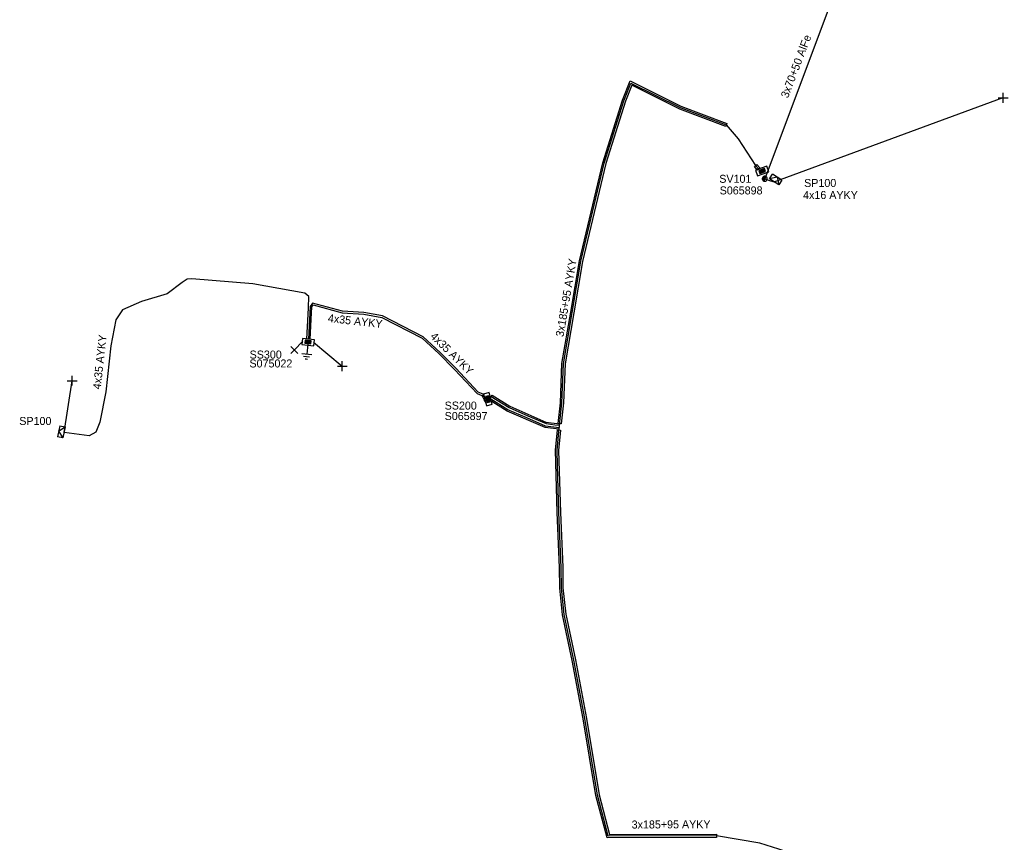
# Model space of a CAD drawing. Extents: x -788458 to -786145, y -1154772 to -1152372.
# Drawn here: x -787489.7 to -787366.2, y -1153095.6 to -1152992.9 of the extents above; entities that cross this region are included whole.
import ezdxf

# ---------------------------------------------------------------- set-up
doc = ezdxf.new("R2010")
doc.units = 0
for name, color, linetype in [('Vrstva 1', 7, 'Continuous'), ('Vrstva 13', 7, 'Continuous'), ('Vrstva 14', 7, 'Continuous'), ('Vrstva 15', 7, 'Continuous'), ('Vrstva 2', 7, 'Continuous'), ('Vrstva 20', 7, 'Continuous'), ('Vrstva 28', 7, 'Continuous'), ('Vrstva 29', 7, 'Continuous'), ('Vrstva 30', 7, 'Continuous'), ('Vrstva 31', 7, 'Continuous'), ('Vrstva 33', 7, 'Continuous'), ('Vrstva 34', 7, 'Continuous'), ('Vrstva 5', 7, 'Continuous'), ('Vrstva 52', 7, 'Continuous'), ('Vrstva 54', 7, 'Continuous'), ('Vrstva 59', 7, 'Continuous'), ('Vrstva 6', 7, 'Continuous'), ('Vrstva 8', 7, 'Continuous'), ('Vrstva 9', 7, 'Continuous')]:
    doc.layers.add(name, color=color, linetype=linetype)

# ---------------------------------------------------------------- blocks, each defined once
blk = doc.blocks.new('NN440')
at = {"layer": 'Vrstva 2'}
for points in [[(0.63, 0), (0.63, 0.06), (0.62, 0.13), (0.6, 0.19), (0.58, 0.25), (0.55, 0.31), (0.51, 0.37), (0.47, 0.42), (0.42, 0.46), (0.37, 0.51), (0.32, 0.54), (0.26, 0.57), (0.2, 0.59), (0.13, 0.61), (0.07, 0.62), (0, 0.63), (-0.06, 0.62), (-0.13, 0.61), (-0.19, 0.59), (-0.26, 0.57), (-0.31, 0.54), (-0.37, 0.51), (-0.42, 0.46), (-0.47, 0.42), (-0.51, 0.37), (-0.54, 0.31), (-0.57, 0.25), (-0.6, 0.19), (-0.62, 0.13), (-0.63, 0.06), (-0.63, 0), (-0.63, -0.07), (-0.62, -0.14), (-0.6, -0.2), (-0.57, -0.26), (-0.54, -0.32), (-0.51, -0.37), (-0.47, -0.43), (-0.42, -0.47), (-0.37, -0.51), (-0.31, -0.55), (-0.26, -0.58), (-0.19, -0.6), (-0.13, -0.62), (-0.06, -0.63), (0, -0.63), (0.07, -0.63), (0.13, -0.62), (0.2, -0.6), (0.26, -0.58), (0.32, -0.55), (0.37, -0.51), (0.42, -0.47), (0.47, -0.43), (0.51, -0.37), (0.55, -0.32), (0.58, -0.26), (0.6, -0.2), (0.62, -0.14), (0.63, -0.07), (0.63, 0)], [(-0.63, 0), (0.63, 0)], [(-0.6, -0.18), (0.57, -0.18)], [(-0.51, -0.32), (0.5, -0.32)], [(-0.37, -0.47), (0.35, -0.47)]]:
    blk.add_lwpolyline(points, dxfattribs=at)
blk = doc.blocks.new('NN800')
at = {"layer": 'Vrstva 1'}
for points in [[(-0.44, 0.44), (0.44, -0.44)], [(-0.44, -0.44), (0.44, 0.44)]]:
    blk.add_lwpolyline(points, dxfattribs=at)
blk = doc.blocks.new('NN620')
at = {"layer": 'Vrstva 8'}
for points in [[(0.75, 0), (-0.75, 0)], [(-0.75, 0), (-0.75, -0.75)], [(0.75, -0.75), (0.75, 0)], [(-0.75, -0.75), (0.75, -0.75)], [(0.37, -0.18), (-0.38, -0.18)], [(-0.38, -0.18), (-0.38, -0.56)], [(-0.38, -0.56), (0.37, -0.56)], [(0.32, -0.23), (-0.33, -0.23)], [(-0.33, -0.23), (-0.33, -0.51)], [(-0.33, -0.51), (0.32, -0.51)], [(0.27, -0.27), (-0.28, -0.27)], [(-0.28, -0.27), (-0.28, -0.46)], [(-0.28, -0.46), (0.27, -0.46)], [(0.23, -0.32), (-0.23, -0.32)], [(-0.23, -0.32), (-0.23, -0.42)], [(-0.23, -0.42), (0.23, -0.42)], [(-0.19, -0.37), (0.19, -0.37)], [(0.23, -0.42), (0.23, -0.32)], [(0.27, -0.46), (0.27, -0.27)], [(0.32, -0.51), (0.32, -0.23)], [(0.37, -0.56), (0.37, -0.18)]]:
    blk.add_lwpolyline(points, dxfattribs=at)
blk = doc.blocks.new('NN630')
at = {"layer": 'Vrstva 9'}
for points in [[(0, -0.7), (-0.7, 0)], [(-0.7, -0.7), (-0.7, 0), (0.7, 0), (0.7, -0.7)], [(-0.7, -0.7), (0.7, -0.7)], [(0, -0.7), (0.7, 0)]]:
    blk.add_lwpolyline(points, dxfattribs=at)
blk = doc.blocks.new('NN810')
at = {"layer": 'Vrstva 14'}
for points in [[(0, -0.64), (0, -1.89)], [(0.63, -1.89), (-0.62, -1.89)], [(0.39, -2.2), (-0.4, -2.2)], [(0, -2.52), (-0.12, -2.52)], [(0.14, -2.52), (0, -2.52)]]:
    blk.add_lwpolyline(points, dxfattribs=at)

msp = doc.modelspace()

# ---------------------------------------------------------------- linework, layer by layer
at = {"layer": 'Vrstva 1'}
msp.add_lwpolyline([(-787370.96, -1152932.92), (-787380.7, -1152966.52), (-787386.85, -1152986.69), (-787396.63, -1153012.79)], dxfattribs=at)
at = {"layer": 'Vrstva 20'}
for points in [[(-787401.51, -1153006.26), (-787407.26, -1153004.1), (-787413.24, -1153001.12), (-787414.03, -1153003.12), (-787416.5, -1153010.9), (-787417.95, -1153017.02), (-787419.39, -1153023.13), (-787420.49, -1153029.52), (-787421.58, -1153035.9), (-787421.77, -1153040.78), (-787422.07, -1153043.37), (-787422.46, -1153043.33), (-787422.17, -1153040.76), (-787421.98, -1153035.86), (-787420.88, -1153029.45), (-787419.79, -1153023.05), (-787418.33, -1153016.92), (-787416.88, -1153010.8), (-787414.41, -1153002.98), (-787413.46, -1153000.56), (-787407.12, -1153003.73), (-787401.37, -1153005.88)], [(-787397.94, -1153011.27), (-787397.64, -1153011.01), (-787397.25, -1153011.44), (-787397.55, -1153011.71)], [(-787422.28, -1153043.37), (-787422.37, -1153044.07), (-787424.07, -1153043.85), (-787428.81, -1153041.81), (-787431.06, -1153040.41), (-787430.69, -1153039.82), (-787428.49, -1153041.19), (-787423.98, -1153043.16)], [(-787422.14, -1153044.18), (-787422.38, -1153046.7), (-787422.17, -1153054.45), (-787421.86, -1153061.3), (-787421.84, -1153063.88), (-787421.48, -1153067.16), (-787420.28, -1153072.86), (-787418.92, -1153080.16), (-787417.34, -1153089.71), (-787416.03, -1153094.66), (-787402.68, -1153094.61), (-787402.68, -1153095.01), (-787416.33, -1153095.06), (-787417.74, -1153089.79), (-787419.32, -1153080.23), (-787420.68, -1153072.94), (-787421.88, -1153067.22), (-787422.24, -1153063.9), (-787422.26, -1153061.31), (-787422.57, -1153054.47), (-787422.78, -1153046.66), (-787422.54, -1153044.14)]]:
    msp.add_lwpolyline(points, close=True, dxfattribs=at)
at = {"layer": 'Vrstva 5'}
for points in [[(-787431.65, -1153040.24), (-787431.28, -1153040.13), (-787430.8, -1153039.99), (-787428.58, -1153041.37), (-787426.25, -1153042.37), (-787423.93, -1153043.36), (-787422.85, -1153043.51), (-787422.28, -1153043.57), (-787421.97, -1153040.77), (-787421.78, -1153035.88), (-787420.68, -1153029.48), (-787419.59, -1153023.09), (-787418.14, -1153016.97), (-787416.69, -1153010.85), (-787414.22, -1153003.05), (-787413.35, -1153000.84), (-787407.2, -1153003.91), (-787401.44, -1153006.07), (-787399.94, -1153007.83), (-787397.79, -1153011.14), (-787397.35, -1153011.64)], [(-787431.68, -1153040), (-787431.83, -1153039.7), (-787432.44, -1153039.43), (-787435.24, -1153036.45), (-787437.19, -1153034.47), (-787439.31, -1153032.52), (-787444.4, -1153029.91), (-787446.7, -1153029.5), (-787449.37, -1153029.32), (-787453.12, -1153028.31), (-787453.4, -1153028.74), (-787453.63, -1153032.82)], [(-787453.43, -1153032.85), (-787453.29, -1153030.34), (-787453.2, -1153028.8), (-787453.04, -1153028.55), (-787449.41, -1153029.52), (-787446.72, -1153029.7), (-787444.46, -1153030.11), (-787439.43, -1153032.68), (-787437.33, -1153034.61), (-787435.38, -1153036.59), (-787432.56, -1153039.59), (-787431.97, -1153039.86), (-787431.86, -1153040.08), (-787431.45, -1153040.91)], [(-787389.72, -1153098.67), (-787389.51, -1153097.98), (-787391.02, -1153097.62), (-787392.53, -1153097.26), (-787394.89, -1153096.49), (-787397.24, -1153095.72), (-787399.96, -1153095.27), (-787402.68, -1153094.81), (-787416.18, -1153094.86), (-787417.54, -1153089.75), (-787419.12, -1153080.19), (-787420.48, -1153072.9), (-787421.68, -1153067.19), (-787422.04, -1153063.89), (-787422.06, -1153061.31), (-787422.37, -1153054.46), (-787422.52, -1153048.57), (-787422.58, -1153046.67), (-787422.31, -1153043.87), (-787424.01, -1153043.66), (-787426.37, -1153042.64), (-787428.72, -1153041.63), (-787430.84, -1153040.31), (-787431.72, -1153040.55)]]:
    msp.add_lwpolyline(points, dxfattribs=at)
at = {"layer": 'Vrstva 52'}
for points in [[(-787396.63, -1153012.79), (-787395.93, -1153013.04), (-787395.46, -1153013.18)], [(-787453.83, -1153032.81), (-787453.61, -1153028.9), (-787453.58, -1153027.48), (-787454.09, -1153027.06), (-787460.59, -1153025.91), (-787468.21, -1153025.3), (-787468.77, -1153025.33), (-787469.4, -1153025.75), (-787471.27, -1153027.17), (-787474.48, -1153028.11), (-787476.84, -1153029.16), (-787477.69, -1153030.41), (-787478.31, -1153033.64), (-787478.95, -1153039.4), (-787479.67, -1153043.2), (-787480.19, -1153044.42), (-787481.03, -1153044.9), (-787484.16, -1153044.46)]]:
    msp.add_lwpolyline(points, dxfattribs=at)
at = {"layer": 'Vrstva 59'}
for points in [[(-787395.46, -1153013.18), (-787366.85, -1153002.67)], [(-787454.34, -1153033.07), (-787455.41, -1153034.18)], [(-787453.02, -1153033.18), (-787449.4, -1153036.18)], [(-787484.16, -1153044.46), (-787483.13, -1153038)]]:
    msp.add_lwpolyline(points, dxfattribs=at)

# ---------------------------------------------------------------- block references
at = {"layer": 'Vrstva 13', "xscale": 0.5, "yscale": 0.5000000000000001, "rotation": -110.69585450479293}
msp.add_blockref('NN440', (-787396.63, -1153012.79), dxfattribs=at)
at = {"layer": 'Vrstva 15', "rotation": -6.237641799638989}
msp.add_blockref('NN810', (-787453.63, -1153032.82), dxfattribs=at)
at = {"layer": 'Vrstva 28'}
for p, rotation in [((-787396.85, -1153012.18), -161.56505096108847), ((-787453.63, -1153032.82), -7.193470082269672), ((-787431.59, -1153040.4), 105.04280072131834)]:
    msp.add_blockref('NN620', p, dxfattribs=dict(at, rotation=rotation))
at = {"layer": 'Vrstva 31'}
for p, rotation in [((-787395.46, -1153013.18), 147.52880762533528), ((-787484.16, -1153044.46), -102.13388025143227)]:
    msp.add_blockref('NN630', p, dxfattribs=dict(at, rotation=rotation))
at = {"layer": 'Vrstva 34'}
for p, rotation in [((-787366.85, -1153002.68), 45), ((-787449.4, -1153036.18), 44.99999995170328), ((-787483.13, -1153038), 45)]:
    msp.add_blockref('NN800', p, dxfattribs=dict(at, rotation=rotation))
msp.add_blockref('NN800', (-787455.41, -1153034.18), dxfattribs=at)

# ---------------------------------------------------------------- texts
at = {"layer": 'Vrstva 2'}
msp.add_text('3x70+50 AlFe', height=1, rotation=69.214, dxfattribs=at).set_placement((-787393.74, -1153002.8))
at = {"layer": 'Vrstva 29'}
for s, p in [('S065898', (-787402.27, -1153014.75)), ('S075022', (-787461, -1153036.35)), ('S065897', (-787436.62, -1153042.91))]:
    msp.add_text(s, height=1, dxfattribs=at).set_placement(p)
at = {"layer": 'Vrstva 30'}
for s, p in [('SV101', (-787402.32, -1153013.3)), ('SS300', (-787460.98, -1153035.24)), ('SS200', (-787436.62, -1153041.61))]:
    msp.add_text(s, height=1, dxfattribs=at).set_placement(p)
at = {"layer": 'Vrstva 33'}
for p in [(-787391.72, -1153013.82), (-787489.75, -1153043.53)]:
    msp.add_text('SP100', height=1, dxfattribs=at).set_placement(p)
at = {"layer": 'Vrstva 54'}
msp.add_text('4x16 AYKY', height=1, dxfattribs=at).set_placement((-787391.85, -1153015.32))
msp.add_text('4x35 AYKY', height=1, rotation=83.66, dxfattribs=at).set_placement((-787479.58, -1153039.12))
at = {"layer": 'Vrstva 6'}
for s, rotation, p in [('3x185+95 AYKY', 80.284, (-787421.78, -1153032.59)), ('4x35 AYKY', 353.648, (-787451.24, -1153030.67)), ('4x35 AYKY', 315.554, (-787438.5, -1153032.56)), ('3x185+95 AYKY', 0.212, (-787413.26, -1153093.91))]:
    msp.add_text(s, height=1, rotation=rotation, dxfattribs=at).set_placement(p)

doc.saveas('drawing.dxf')
